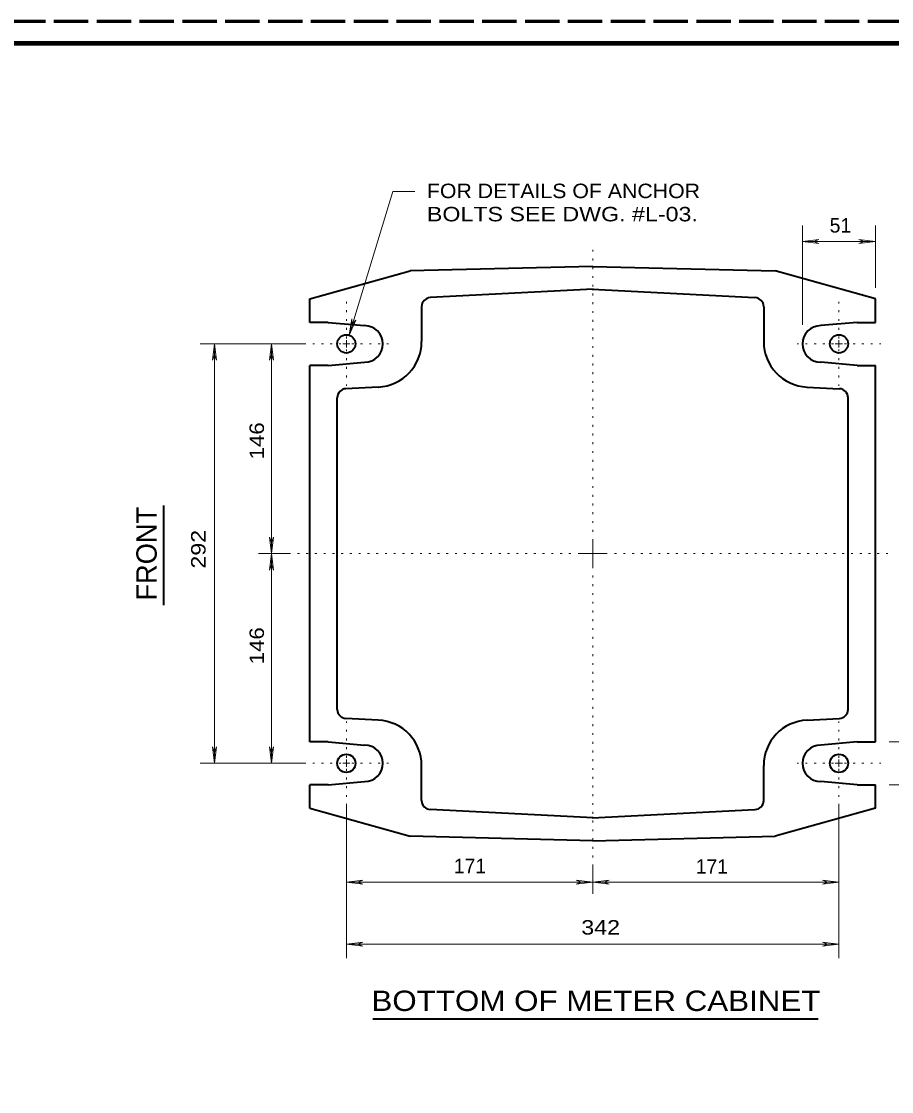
# Model space of a CAD drawing. Extents: x 312583 to 312853, y 144419 to 144586.
# Drawn here: x 312672.7 to 312718.5, y 144530 to 144586.2 of the extents above; entities that cross this region are included whole.
import ezdxf
from ezdxf.enums import TextEntityAlignment as Align

# ---------------------------------------------------------------- set-up
doc = ezdxf.new("R2010")
doc.units = 0
doc.header["$LTSCALE"] = 0.3
doc.linetypes.add('DOTTED', pattern=[1.5, 0.3, -1.2])
doc.linetypes.add('LONG_DASHED', pattern=[7.5, 6, -1.5])
doc.layers.add('1', color=7, linetype='Continuous', lineweight=13)

msp = doc.modelspace()

# ---------------------------------------------------------------- linework, layer by layer
at = {"layer": '1', "linetype": 'LONG_DASHED', "lineweight": 60}
msp.add_line((312851.75, 144586.2246), (312583.526, 144586.2246), dxfattribs=at)
msp.add_line((312851.75, 144586.2246), (312583.526, 144586.2246), dxfattribs=at)
at = {"layer": '1'}
for p, q in [((312713.7676, 144570.2833), (312713.7676, 144575.4966)), ((312717.601, 144572.2306), (312717.601, 144575.4966)), ((312713.7676, 144574.6533), (312714.634, 144574.7606)), ((312713.7676, 144574.6533), (312717.601, 144574.6533)), ((312713.7676, 144574.6533), (312714.634, 144574.5459)), ((312714.634, 144574.7606), (312714.358, 144574.6533)), ((312714.634, 144574.5459), (312714.358, 144574.6533)), ((312716.7346, 144574.7606), (312717.0106, 144574.6533)), ((312717.601, 144574.6533), (312716.7346, 144574.7606)), ((312716.7346, 144574.5459), (312717.0106, 144574.6533)), ((312717.601, 144574.6533), (312716.7346, 144574.5459)), ((312689.955, 144569.7313), (312690.1006, 144570.5976)), ((312689.955, 144569.7313), (312690.3076, 144570.5286)), ((312690.1006, 144570.5976), (312690.1236, 144570.2986)), ((312690.3076, 144570.5286), (312690.1236, 144570.2986)), ((312687.609, 144569.2789), (312682.1273, 144569.2789)), ((312682.8863, 144569.2789), (312682.779, 144568.4126)), ((312682.8863, 144547.2373), (312682.8863, 144569.2789)), ((312682.8863, 144569.2789), (312682.9936, 144568.4126)), ((312685.884, 144569.2789), (312685.7766, 144568.4126)), ((312685.884, 144569.2789), (312685.9913, 144568.4126)), ((312689.8093, 144569.2789), (312689.6176, 144569.2789)), ((312689.8093, 144569.2789), (312689.8093, 144569.4706)), ((312689.8093, 144569.2789), (312690.001, 144569.2789)), ((312689.8093, 144569.2789), (312689.8093, 144569.0873)), ((312715.6843, 144569.2789), (312715.4926, 144569.2789)), ((312715.6843, 144569.2789), (312715.6843, 144569.4706)), ((312715.6843, 144569.2789), (312715.876, 144569.2789)), ((312715.6843, 144569.2789), (312715.6843, 144569.0873)), ((312682.779, 144568.4126), (312682.8863, 144568.6886)), ((312682.9936, 144568.4126), (312682.8863, 144568.6886)), ((312685.7766, 144568.4126), (312685.884, 144568.6886)), ((312685.9913, 144568.4126), (312685.884, 144568.6886)), ((312685.7766, 144559.1206), (312685.884, 144558.8446)), ((312685.884, 144558.2543), (312685.7766, 144559.1206)), ((312685.9913, 144559.1206), (312685.884, 144558.8446)), ((312685.884, 144558.2543), (312685.9913, 144559.1206)), ((312702.7506, 144558.2543), (312702.7506, 144559.0209)), ((312686.8806, 144558.2543), (312685.194, 144558.2543)), ((312685.884, 144558.2543), (312685.7766, 144557.3879)), ((312685.884, 144558.2543), (312685.9913, 144557.3879)), ((312702.7506, 144558.2543), (312701.984, 144558.2543)), ((312702.7506, 144558.2543), (312703.5173, 144558.2543)), ((312702.7506, 144558.2543), (312702.7506, 144557.4876)), ((312685.7766, 144557.3879), (312685.884, 144557.6639)), ((312685.9913, 144557.3879), (312685.884, 144557.6639)), ((312718.3216, 144548.3643), (312722.9063, 144548.3643)), ((312682.779, 144548.1036), (312682.8863, 144547.8276)), ((312682.8863, 144547.2373), (312682.779, 144548.1036)), ((312682.9936, 144548.1036), (312682.8863, 144547.8276)), ((312682.8863, 144547.2373), (312682.9936, 144548.1036)), ((312685.7766, 144548.1036), (312685.884, 144547.8276)), ((312685.884, 144547.2373), (312685.7766, 144548.1036)), ((312685.9913, 144548.1036), (312685.884, 144547.8276)), ((312685.884, 144547.2373), (312685.9913, 144548.1036)), ((312689.8093, 144547.2373), (312689.8093, 144547.4289)), ((312715.6843, 144547.2373), (312715.6843, 144547.4289)), ((312687.609, 144547.2373), (312682.1273, 144547.2373)), ((312689.8093, 144547.2373), (312689.6176, 144547.2373)), ((312689.8093, 144547.2373), (312690.001, 144547.2373)), ((312689.8093, 144547.2373), (312689.8093, 144547.0456)), ((312715.6843, 144547.2373), (312715.4926, 144547.2373)), ((312715.6843, 144547.2373), (312715.876, 144547.2373)), ((312715.6843, 144547.2373), (312715.6843, 144547.0456)), ((312718.3216, 144546.1026), (312722.9063, 144546.1026)), ((312689.8093, 144545.0293), (312689.8093, 144537.0023)), ((312715.6843, 144545.0293), (312715.6843, 144537.0023)), ((312702.7506, 144541.8323), (312702.7506, 144540.3679)), ((312689.8093, 144540.9889), (312690.6756, 144541.0963)), ((312690.6756, 144541.0963), (312690.3996, 144540.9889)), ((312701.8843, 144541.0963), (312702.1603, 144540.9889)), ((312702.7506, 144540.9889), (312701.8843, 144541.0963)), ((312702.7506, 144540.9889), (312703.617, 144541.0963)), ((312703.617, 144541.0963), (312703.341, 144540.9889)), ((312714.818, 144541.0963), (312715.094, 144540.9889)), ((312715.6843, 144540.9889), (312714.818, 144541.0963)), ((312689.8093, 144540.9889), (312690.6756, 144540.8816)), ((312690.6756, 144540.8816), (312690.3996, 144540.9889)), ((312701.8843, 144540.8816), (312702.1603, 144540.9889)), ((312702.7506, 144540.9889), (312701.8843, 144540.8816)), ((312702.7506, 144540.9889), (312703.617, 144540.8816)), ((312703.617, 144540.8816), (312703.341, 144540.9889)), ((312714.818, 144540.8816), (312715.094, 144540.9889)), ((312715.6843, 144540.9889), (312714.818, 144540.8816)), ((312689.8093, 144537.7229), (312690.6756, 144537.8303)), ((312689.8093, 144537.7229), (312715.6843, 144537.7229)), ((312689.8093, 144537.7229), (312690.6756, 144537.6156)), ((312690.6756, 144537.8303), (312690.3996, 144537.7229)), ((312690.6756, 144537.6156), (312690.3996, 144537.7229)), ((312714.818, 144537.8303), (312715.094, 144537.7229)), ((312715.6843, 144537.7229), (312714.818, 144537.8303)), ((312714.818, 144537.6156), (312715.094, 144537.7229)), ((312715.6843, 144537.7229), (312714.818, 144537.6156))]:
    msp.add_line(p, q, dxfattribs=at)
at = {"layer": '1', "linetype": 'DOTTED'}
for p, q in [((312702.7506, 144559.4043), (312702.7506, 144574.4309)), ((312689.8093, 144569.5626), (312689.8093, 144571.4793)), ((312715.6843, 144569.5626), (312715.6843, 144571.4793)), ((312689.5256, 144569.2789), (312687.609, 144569.2789)), ((312690.1006, 144569.2789), (312692.0173, 144569.2789)), ((312715.4006, 144569.2789), (312713.484, 144569.2789)), ((312715.9756, 144569.2789), (312717.8923, 144569.2789)), ((312689.8093, 144568.9876), (312689.8093, 144567.0709)), ((312715.6843, 144568.9876), (312715.6843, 144567.0709)), ((312701.6006, 144558.2543), (312686.8806, 144558.2543)), ((312703.9006, 144558.2543), (312718.4136, 144558.2543)), ((312702.7506, 144557.1043), (312702.7506, 144541.8323)), ((312689.8093, 144547.5209), (312689.8093, 144549.4376)), ((312715.6843, 144547.5209), (312715.6843, 144549.4376)), ((312689.5256, 144547.2373), (312687.609, 144547.2373)), ((312689.8093, 144546.9459), (312689.8093, 144545.0293)), ((312690.1006, 144547.2373), (312692.0173, 144547.2373)), ((312715.4006, 144547.2373), (312713.484, 144547.2373)), ((312715.6843, 144546.9459), (312715.6843, 144545.0293)), ((312715.9756, 144547.2373), (312717.8923, 144547.2373))]:
    msp.add_line(p, q, dxfattribs=at)
at = {"layer": '1', "lineweight": 40}
for p, q in [((312687.8926, 144571.6479), (312693.1673, 144573.1123)), ((312702.7506, 144573.3499), (312693.1673, 144573.1123)), ((312702.7506, 144573.3499), (312712.334, 144573.1123)), ((312717.601, 144571.6479), (312712.334, 144573.1123)), ((312702.7736, 144572.1539), (312694.2176, 144571.7093)), ((312702.7276, 144572.1539), (312711.276, 144571.7093)), ((312687.8926, 144570.4059), (312687.8926, 144571.6479)), ((312717.601, 144570.4059), (312717.601, 144571.6479)), ((312693.7653, 144571.2263), (312693.7653, 144569.4016)), ((312711.736, 144571.2263), (312711.736, 144569.4016)), ((312688.851, 144570.4059), (312687.8926, 144570.4059)), ((312688.851, 144570.4059), (312690.7676, 144570.2373)), ((312716.6426, 144570.4059), (312714.726, 144570.2373)), ((312716.6426, 144570.4059), (312717.601, 144570.4059)), ((312687.8926, 144548.3643), (312687.8926, 144568.1443)), ((312688.851, 144568.1443), (312687.8926, 144568.1443)), ((312688.851, 144568.1443), (312690.7676, 144568.3206)), ((312716.6426, 144568.1443), (312714.726, 144568.3206)), ((312716.6426, 144568.1443), (312717.601, 144568.1443)), ((312717.601, 144548.3643), (312717.601, 144568.1443)), ((312691.4883, 144567.0096), (312689.7863, 144566.9176)), ((312714.0053, 144567.0096), (312715.7073, 144566.9176)), ((312689.334, 144550.0663), (312689.334, 144566.4423)), ((312716.1673, 144550.0663), (312716.1673, 144566.4423)), ((312691.4883, 144549.5066), (312689.7863, 144549.5909)), ((312714.0053, 144549.5066), (312715.7073, 144549.5909)), ((312688.851, 144548.3643), (312687.8926, 144548.3643)), ((312688.851, 144548.3643), (312690.7676, 144548.1956)), ((312716.6426, 144548.3643), (312714.726, 144548.1956)), ((312716.6426, 144548.3643), (312717.601, 144548.3643)), ((312693.7653, 144545.2823), (312693.7653, 144547.1146)), ((312711.736, 144545.2823), (312711.736, 144547.1146)), ((312688.851, 144546.1026), (312690.7676, 144546.2789)), ((312716.6426, 144546.1026), (312714.726, 144546.2789)), ((312687.8926, 144544.8683), (312687.8926, 144546.1026)), ((312688.851, 144546.1026), (312687.8926, 144546.1026)), ((312716.6426, 144546.1026), (312717.601, 144546.1026)), ((312717.601, 144544.8683), (312717.601, 144546.1026)), ((312687.8926, 144544.8683), (312693.1673, 144543.4039)), ((312702.7736, 144544.3623), (312694.2176, 144544.7993)), ((312702.7276, 144544.3623), (312711.276, 144544.8069)), ((312717.601, 144544.8683), (312712.334, 144543.4039)), ((312702.7506, 144543.1586), (312693.1673, 144543.4039)), ((312702.7506, 144543.1586), (312712.334, 144543.4039))]:
    msp.add_line(p, q, dxfattribs=at)
at = {"layer": '1', "lineweight": 35}
for p, q in [((312680.226, 144555.5403), (312680.226, 144560.7766)), ((312691.1984, 144533.8011), (312714.5999, 144533.8011))]:
    msp.add_line(p, q, dxfattribs=at)
at = {"layer": '1', "lineweight": 158}
msp.add_lwpolyline([(312616.5, 144423.1446), (312616.5, 144585.0846), (312849, 144585.0846)], dxfattribs=at)
at = {"layer": '1'}
for points in [[(312689.955, 144569.7313), (312692.255, 144577.2906), (312693.4126, 144577.2906)], [(312685.884, 144547.2373), (312685.884, 144558.2543), (312685.884, 144569.2789)], [(312689.8093, 144540.9889), (312702.7506, 144540.9889), (312715.6843, 144540.9889)]]:
    msp.add_lwpolyline(points, dxfattribs=at)
at = {"layer": '1', "lineweight": 40}
for centre in [(312689.8112, 144569.277), (312715.6862, 144569.277), (312689.8112, 144547.2354), (312715.6862, 144547.2354)]:
    msp.add_circle(centre, 0.4792, dxfattribs=at)
for centre, radius, start, end in [((312694.2445, 144571.2287), 0.4792, 92.9765, 180), ((312711.253, 144571.2287), 0.4792, 0, 87.0235), ((312690.7696, 144569.277), 0.9583, 270, 90), ((312714.7279, 144569.277), 0.9583, 90, 270), ((312691.3695, 144569.4004), 2.3958, 272.86241, 0), ((312714.128, 144569.4004), 2.3958, 180, 267.13759), ((312689.8112, 144566.4438), 0.4792, 92.88828, 180), ((312715.6862, 144566.4438), 0.4792, 0, 87.11172), ((312689.8112, 144550.0685), 0.4792, 180, 267.11172), ((312715.6862, 144550.0685), 0.4792, 272.88828, 0), ((312691.3695, 144547.1119), 2.3958, 0, 87.13759), ((312714.128, 144547.1119), 2.3958, 92.86241, 180), ((312690.7696, 144547.2354), 0.9583, 270, 90), ((312714.7279, 144547.2354), 0.9583, 90, 270), ((312694.2445, 144545.2818), 0.4792, 180, 267.03604), ((312711.253, 144545.2837), 0.4792, 272.9765, 0)]:
    msp.add_arc(centre, radius, start, end, dxfattribs=at)

# ---------------------------------------------------------------- texts
at = {"layer": '1'}
for s, width, p in [('FOR DETAILS OF ANCHOR', 1.1, (312694.0413, 144576.9369)), ('BOLTS SEE DWG. #L-03.', 1.2, (312694.0413, 144575.7169)), ('342 ', 1.2, (312702.1504, 144538.2331))]:
    msp.add_text(s, height=0.76, dxfattribs=dict(at, width=width)).set_placement(p)
for s, p in [('51 ', (312715.1978, 144575.1251)), ('171  ', (312695.4554, 144541.4607)), ('171  ', (312708.1625, 144541.4312))]:
    msp.add_text(s, height=0.76, dxfattribs=at).set_placement(p)
for s, width, p in [('146 ', 1.15, (312685.4833, 144563.2048)), ('292 ', 1.2, (312682.4156, 144557.4661)), ('146 ', 1.15, (312685.4834, 144552.4351))]:
    msp.add_text(s, height=0.76, rotation=90, dxfattribs=dict(at, width=width)).set_placement(p)
msp.add_text('FRONT', height=1.07, rotation=90, dxfattribs=at).set_placement((312679.8484, 144558.2494), align=Align.CENTER)
at = {"layer": '1', "width": 1.15}
msp.add_text('BOTTOM OF METER CABINET', height=1.07, dxfattribs=at).set_placement((312702.9195, 144534.2179), align=Align.CENTER)

doc.saveas('drawing.dxf')
